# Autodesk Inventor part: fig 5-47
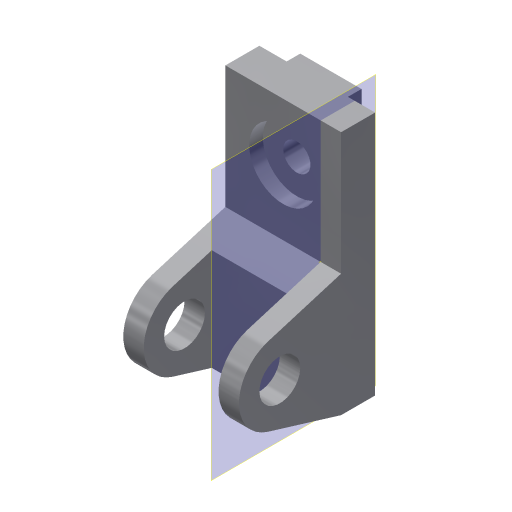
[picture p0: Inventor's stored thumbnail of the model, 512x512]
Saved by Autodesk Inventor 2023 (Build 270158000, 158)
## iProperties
Created: 2001-11
Part Number: fig 5-47
Document SubType Name: Modeling
Designer: Renu Muthoo
Density: 1 g/cm^3
Material: Generic
Appearance: Aluminum - Flat
Control State: 0
Master: False
Checked Out: False
Shininess: 65.0
Angle Display Precision: 2
Document Length Units: 11269
Document Angle Units: 11279
Document Time Units: 11290
Document Mass Units: 11283
Document Length Units Precision: 3
Document Angle Units Precision: 2
Density: 0.0
Volumn: 0.0
Area: 0.0
PropertySet Name: Model Information
Author: Renu Muthoo
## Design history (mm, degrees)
node "Sketch1"
sketch "Sketch2"
  geometry: L1 (33.257, 104.664)-(33.257, -75.336); L2 (33.257, -75.336)-(8.257, -75.336); L3 (8.257, -75.336)-(-45.451, -59.045); L4 (-45.451, -1.628)-(8.257, 14.664); L5 (8.257, 14.664)-(8.257, 104.664); L6 (8.257, 104.664)-(33.257, 104.664); C1 r 15 at (-36.743, -30.336); A1 r 30 centre (-36.743, -30.336) between (-45.451, -1.628) and (-45.451, -59.045)
  constraints: 12 end point, 2 centre point, 2 equal length, 2 parallel, 2 point on circle, 2 tangent, 1 coincident, 1 perpendicular, 1 vertical
  dimensions: "d0" = 180 distance of L1.start L1.end; "d1" = 30 radius of A1; "d2" = 25 distance of L5.end L1.start; "d3" = 45 distance from line of L2 A1.centre; "d4" = 70 distance from line of L1 A1.centre; "d5" = 30 diameter of C1
extrude "Extrusion1" new body sketch "Sketch2" distance "d6" = 85; taper "d7" = 0 deg
workplane "Work Plane1"
sketch "Sketch3"
  geometry: L1 (15, 62.364)-(70, 62.364); L2 (70, 62.364)-(70, -52.386); L3 (70, -52.386)-(15, -52.386); L4 (15, -52.386)-(15, 62.364); L5 (0, -45)-(0, -28.708) reference
  constraints: 8 end point, 2 parallel, 1 horizontal, 1 perpendicular
  dimensions: "d8" = 55 distance of L1.start L1.end; "d9" = 15 distance between parallel lines of L5 L4
extrude "Extrusion2" cut sketch "Sketch3" distance "d10" = 50; taper "d11" = 0 deg
sketch "Sketch4"
  geometry: L1 (0, 25)-(85, 25) reference; L2 (0, 0)-(0, 25) reference; L3 (20, 25)-(65, 25); L4 (65, 25)-(65, 35); L5 (65, 35)-(20, 35); L6 (20, 35)-(20, 25)
  constraints: 8 end point, 2 parallel, 1 horizontal, 1 perpendicular, 1 point on line
  dimensions: "d12" = 45 distance of L4.end L5.end; "d13" = 10 distance of L3.end L4.end; "d14" = 20 distance between parallel lines of L2 L6
extrude "Extrusion3" join sketch "Sketch4" stored distance "d15" = 50; taper "d16" = 0 deg
sketch "Sketch5"
  geometry: L1 (85, 0)-(85, 90) reference; L2 (0, 90)-(85, 90) reference; 1 further point
  dimensions: "d17" = 42 distance from line of L2 point (42.5, 48); "d18" = 42.5 distance from line of L1 point (42.5, 48)
hole "Hole1" sketch "Sketch5" at (42.5, 48) diameter "d19" = 20; stored, may be unused: countersink angle "d23" = 82 deg, drill point angle "d25" = 118 deg; dims "d20" = 6, "d21" = 50, "d22" = 10, "d24" = 8
workplane "Work Plane7"
workpoint "Work Point7"
workpoint "Work Point8"
body "Solid1"
other parameters: "d29" = 0
